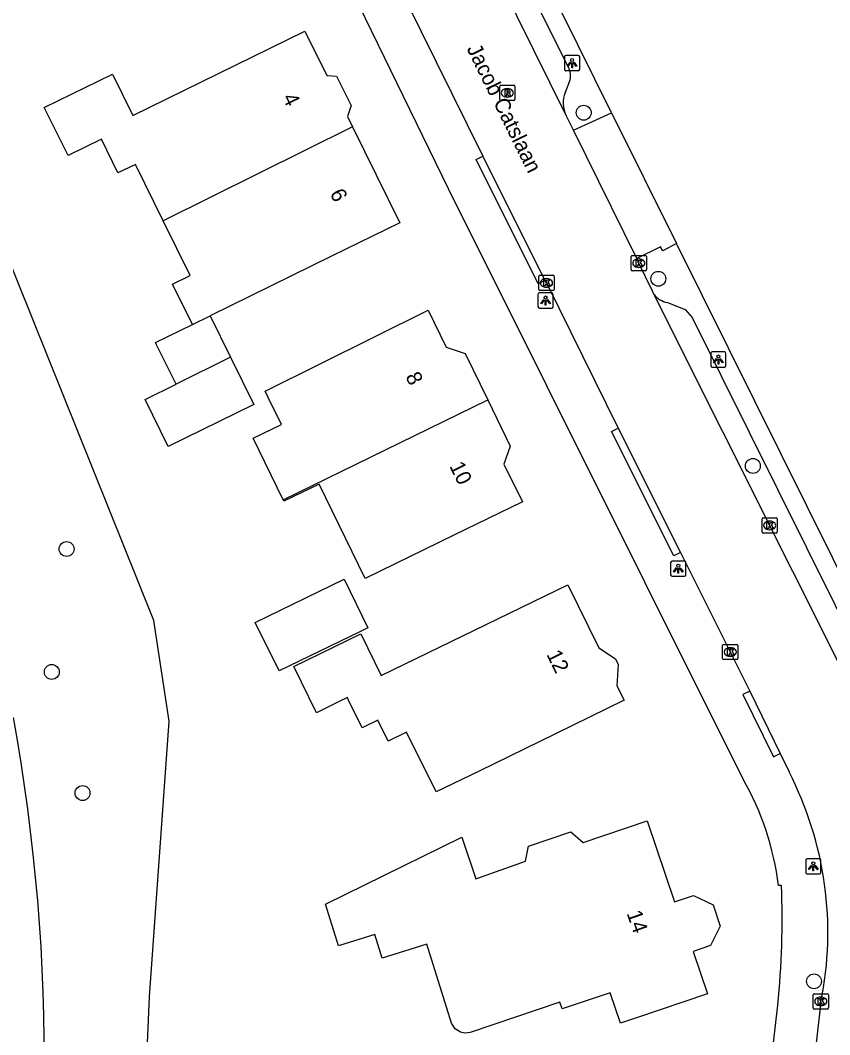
# Model space of a CAD drawing. Extents: x 161354 to 161876, y 382161 to 382804.
# Drawn here: x 161421.9 to 161475, y 382389.5 to 382456.1 of the extents above; entities that cross this region are included whole.
import ezdxf

# ---------------------------------------------------------------- set-up
doc = ezdxf.new("R2010")
doc.units = 0
for name, color, linetype in [('IMGEO_Boom', 7, 'Continuous'), ('IMGEO_Gemengd_bos', 7, 'Continuous'), ('IMGEO_Kolk', 7, 'Continuous'), ('IMGEO_Lichtpunt', 7, 'Continuous'), ('IMGEO_Openbare_ruimte_label', 7, 'Continuous'), ('IMGEO_Pand', 7, 'Continuous'), ('IMGEO_Pand_nummerreeks', 7, 'Continuous'), ('IMGEO_Rijbaan_lokaal_open', 7, 'Continuous'), ('IMGEO_Rioolput', 7, 'Continuous'), ('IMGEO_Voetpad_gesloten', 7, 'Continuous'), ('IMGEO_Voetpad_open', 7, 'Continuous')]:
    doc.layers.add(name, color=color, linetype=linetype)

msp = doc.modelspace()

# ---------------------------------------------------------------- linework, layer by layer
at = {"layer": 'IMGEO_Boom'}
for centre in [(161458.85, 382449.996), (161463.744, 382439.091), (161469.949, 382426.805), (161424.908, 382421.348), (161423.939, 382413.276), (161425.955, 382405.325), (161473.963, 382392.963)]:
    msp.add_circle(centre, 0.489, dxfattribs=at)
at = {"layer": 'IMGEO_Gemengd_bos'}
msp.add_lwpolyline([(161435.54, 382329.392), (161434.865, 382334.273), (161432.222, 382351.93), (161428.6, 382351.546), (161430.361, 382391.947), (161431.642, 382410.034), (161430.625, 382416.654), (161414.695, 382456.317), (161414.039, 382457.95), (161407.235, 382474.367), (161405.55, 382478.433), (161404.982, 382479.804)], dxfattribs=at)
at = {"layer": 'IMGEO_Kolk'}
for p, q in [((161461.963, 382439.692), (161461.963, 382440.544)), ((161462.038, 382440.618), (161462.89, 382440.618)), ((161462.964, 382440.544), (161462.964, 382439.692)), ((161462.474, 382439.838), (161462.449, 382439.838)), ((161462.451, 382440.398), (161462.476, 382440.398)), ((161455.902, 382438.394), (161455.902, 382439.246)), ((161455.977, 382439.32), (161456.829, 382439.32)), ((161456.903, 382439.246), (161456.903, 382438.394)), ((161462.89, 382439.618), (161462.038, 382439.618)), ((161456.413, 382438.54), (161456.388, 382438.54)), ((161456.39, 382439.1), (161456.415, 382439.1)), ((161456.829, 382438.32), (161455.977, 382438.32)), ((161470.553, 382422.471), (161470.553, 382423.323)), ((161470.628, 382423.397), (161471.48, 382423.397)), ((161471.041, 382423.177), (161471.066, 382423.177)), ((161471.554, 382423.323), (161471.554, 382422.471)), ((161471.064, 382422.617), (161471.039, 382422.617)), ((161471.48, 382422.397), (161470.628, 382422.397)), ((161467.966, 382414.16), (161467.966, 382415.012)), ((161468.041, 382415.086), (161468.893, 382415.086)), ((161468.454, 382414.866), (161468.479, 382414.866)), ((161468.967, 382415.012), (161468.967, 382414.16)), ((161468.893, 382414.086), (161468.041, 382414.086)), ((161468.477, 382414.306), (161468.452, 382414.306)), ((161473.906, 382391.218), (161473.906, 382392.07)), ((161473.981, 382392.144), (161474.833, 382392.144)), ((161474.394, 382391.924), (161474.419, 382391.924)), ((161474.907, 382392.07), (161474.907, 382391.218)), ((161474.417, 382391.364), (161474.392, 382391.364)), ((161474.833, 382391.144), (161473.981, 382391.144))]:
    msp.add_line(p, q, dxfattribs=at)
for points in [[(161461.963, 382439.692), (161461.963, 382440.544)], [(161462.038, 382440.618), (161462.89, 382440.618)], [(161462.964, 382440.544), (161462.964, 382439.692)], [(161462.284, 382440.318), (161462.407, 382440.318), (161462.407, 382440.167), (161462.537, 382440.318), (161462.701, 382440.318), (161462.555, 382440.167), (161462.708, 382439.918), (161462.556, 382439.918), (161462.471, 382440.082), (161462.407, 382440.015), (161462.407, 382439.918), (161462.284, 382439.918), (161462.284, 382440.318)], [(161455.902, 382438.394), (161455.902, 382439.246)], [(161455.977, 382439.32), (161456.829, 382439.32)], [(161456.903, 382439.246), (161456.903, 382438.394)], [(161462.89, 382439.618), (161462.038, 382439.618)], [(161456.223, 382439.02), (161456.346, 382439.02), (161456.346, 382438.869), (161456.476, 382439.02), (161456.64, 382439.02), (161456.494, 382438.869), (161456.647, 382438.62), (161456.495, 382438.62), (161456.41, 382438.784), (161456.346, 382438.717), (161456.346, 382438.62), (161456.223, 382438.62), (161456.223, 382439.02)], [(161456.829, 382438.32), (161455.977, 382438.32)], [(161470.553, 382422.471), (161470.553, 382423.323)], [(161470.628, 382423.397), (161471.48, 382423.397)], [(161471.554, 382423.323), (161471.554, 382422.471)], [(161470.874, 382423.097), (161470.997, 382423.097), (161470.997, 382422.946), (161471.127, 382423.097), (161471.291, 382423.097), (161471.145, 382422.946), (161471.298, 382422.697), (161471.146, 382422.697), (161471.061, 382422.861), (161470.997, 382422.794), (161470.997, 382422.697), (161470.874, 382422.697), (161470.874, 382423.097)], [(161471.48, 382422.397), (161470.628, 382422.397)], [(161467.966, 382414.16), (161467.966, 382415.012)], [(161468.041, 382415.086), (161468.893, 382415.086)], [(161468.287, 382414.786), (161468.41, 382414.786), (161468.41, 382414.635), (161468.54, 382414.786), (161468.704, 382414.786), (161468.558, 382414.635), (161468.711, 382414.386), (161468.559, 382414.386), (161468.474, 382414.55), (161468.41, 382414.483), (161468.41, 382414.386), (161468.287, 382414.386), (161468.287, 382414.786)], [(161468.967, 382415.012), (161468.967, 382414.16)], [(161468.893, 382414.086), (161468.041, 382414.086)], [(161473.906, 382391.218), (161473.906, 382392.07)], [(161473.981, 382392.144), (161474.833, 382392.144)], [(161474.907, 382392.07), (161474.907, 382391.218)], [(161474.227, 382391.844), (161474.35, 382391.844), (161474.35, 382391.693), (161474.48, 382391.844), (161474.644, 382391.844), (161474.498, 382391.693), (161474.651, 382391.444), (161474.499, 382391.444), (161474.414, 382391.608), (161474.35, 382391.541), (161474.35, 382391.444), (161474.227, 382391.444), (161474.227, 382391.844)], [(161474.833, 382391.144), (161473.981, 382391.144)]]:
    msp.add_lwpolyline(points, dxfattribs=at)
for centre, start, end in [((161462.04, 382440.542), 91.55205, 178.44795), ((161462.04, 382440.542), 91.55205, 178.44795), ((161462.888, 382440.542), 1.55205, 88.44795), ((161462.888, 382440.542), 1.55205, 88.44795), ((161455.979, 382439.244), 91.55205, 178.44795), ((161455.979, 382439.244), 91.55205, 178.44795), ((161456.827, 382439.244), 1.55205, 88.44795), ((161456.827, 382439.244), 1.55205, 88.44795), ((161462.04, 382439.694), 181.55205, 268.44795), ((161462.04, 382439.694), 181.55205, 268.44795), ((161462.888, 382439.694), 271.55205, 358.44795), ((161462.888, 382439.694), 271.55205, 358.44795), ((161455.979, 382438.396), 181.55205, 268.44795), ((161455.979, 382438.396), 181.55205, 268.44795), ((161456.827, 382438.396), 271.55205, 358.44795), ((161456.827, 382438.396), 271.55205, 358.44795), ((161470.63, 382423.321), 91.55205, 178.44795), ((161470.63, 382423.321), 91.55205, 178.44795), ((161471.478, 382423.321), 1.55205, 88.44795), ((161471.478, 382423.321), 1.55205, 88.44795), ((161470.63, 382422.473), 181.55205, 268.44795), ((161470.63, 382422.473), 181.55205, 268.44795), ((161471.478, 382422.473), 271.55205, 358.44795), ((161471.478, 382422.473), 271.55205, 358.44795), ((161468.043, 382415.01), 91.55205, 178.44795), ((161468.043, 382415.01), 91.55205, 178.44795), ((161468.891, 382415.01), 1.55205, 88.44795), ((161468.891, 382415.01), 1.55205, 88.44795), ((161468.043, 382414.162), 181.55205, 268.44795), ((161468.043, 382414.162), 181.55205, 268.44795), ((161468.891, 382414.162), 271.55205, 358.44795), ((161468.891, 382414.162), 271.55205, 358.44795), ((161473.983, 382392.068), 91.55205, 178.44795), ((161473.983, 382392.068), 91.55205, 178.44795), ((161474.831, 382392.068), 1.55205, 88.44795), ((161474.831, 382392.068), 1.55205, 88.44795), ((161473.983, 382391.22), 181.55205, 268.44795), ((161473.983, 382391.22), 181.55205, 268.44795), ((161474.831, 382391.22), 271.55205, 358.44795), ((161474.831, 382391.22), 271.55205, 358.44795)]:
    msp.add_arc(centre, 0.0765, start, end, dxfattribs=at)
for centre, major_axis, ratio, start_param, end_param in [((161462.45, 382440.118), (-0.387, 0.002), 0.722429, 4.712389, 7.853982), ((161462.475, 382440.118), (-0.39, 0.002), 0.717154, 1.570796, 4.712389), ((161456.389, 382438.82), (-0.387, 0.002), 0.722429, 4.712389, 7.853982), ((161456.414, 382438.82), (-0.39, 0.002), 0.717154, 1.570796, 4.712389), ((161471.04, 382422.897), (-0.387, 0.002), 0.722429, 4.712389, 7.853982), ((161471.065, 382422.897), (-0.39, 0.002), 0.717154, 1.570796, 4.712389), ((161468.453, 382414.586), (-0.387, 0.002), 0.722429, 4.712389, 7.853982), ((161468.478, 382414.586), (-0.39, 0.002), 0.717154, 1.570796, 4.712389), ((161474.393, 382391.644), (-0.387, 0.002), 0.722429, 4.712389, 7.853982), ((161474.418, 382391.644), (-0.39, 0.002), 0.717154, 1.570796, 4.712389)]:
    msp.add_ellipse(centre, major_axis=major_axis, ratio=ratio, start_param=start_param, end_param=end_param, dxfattribs=at)
at = {"layer": 'IMGEO_Lichtpunt'}
for p, q in [((161457.588, 382453.658), (161457.588, 382452.851)), ((161457.588, 382453.658), (161457.588, 382452.851)), ((161458.49, 382453.753), (161457.682, 382453.753)), ((161458.49, 382453.753), (161457.682, 382453.753)), ((161458.584, 382452.851), (161458.584, 382453.658)), ((161458.584, 382452.851), (161458.584, 382453.658)), ((161457.682, 382452.757), (161458.49, 382452.757)), ((161457.682, 382452.757), (161458.49, 382452.757)), ((161455.847, 382438.07), (161455.847, 382437.263)), ((161455.847, 382438.07), (161455.847, 382437.263)), ((161456.749, 382438.165), (161455.941, 382438.165)), ((161456.749, 382438.165), (161455.941, 382438.165)), ((161456.843, 382437.263), (161456.843, 382438.07)), ((161456.843, 382437.263), (161456.843, 382438.07)), ((161455.941, 382437.169), (161456.749, 382437.169)), ((161455.941, 382437.169), (161456.749, 382437.169)), ((161467.189, 382434.196), (161467.189, 382433.389)), ((161467.189, 382434.196), (161467.189, 382433.389)), ((161468.091, 382434.291), (161467.283, 382434.291)), ((161468.091, 382434.291), (161467.283, 382434.291)), ((161468.185, 382433.389), (161468.185, 382434.196)), ((161468.185, 382433.389), (161468.185, 382434.196)), ((161467.283, 382433.295), (161468.091, 382433.295)), ((161467.283, 382433.295), (161468.091, 382433.295)), ((161465.456, 382420.555), (161464.648, 382420.555)), ((161465.456, 382420.555), (161464.648, 382420.555)), ((161464.554, 382420.46), (161464.554, 382419.653)), ((161464.554, 382420.46), (161464.554, 382419.653)), ((161465.55, 382419.653), (161465.55, 382420.46)), ((161465.55, 382419.653), (161465.55, 382420.46)), ((161464.648, 382419.559), (161465.456, 382419.559)), ((161464.648, 382419.559), (161465.456, 382419.559)), ((161473.415, 382400.92), (161473.415, 382400.113)), ((161473.415, 382400.92), (161473.415, 382400.113)), ((161474.317, 382401.015), (161473.509, 382401.015)), ((161474.317, 382401.015), (161473.509, 382401.015)), ((161474.411, 382400.113), (161474.411, 382400.92)), ((161474.411, 382400.113), (161474.411, 382400.92)), ((161473.509, 382400.019), (161474.317, 382400.019)), ((161473.509, 382400.019), (161474.317, 382400.019))]:
    msp.add_line(p, q, dxfattribs=at)
for points in [[(161457.962, 382453.322), (161458.001, 382453.294), (161457.813, 382453.032), (161457.775, 382453.059), (161457.962, 382453.322)], [(161458.064, 382453.274), (161458.111, 382453.274), (161458.111, 382452.952), (161458.064, 382452.952), (161458.064, 382453.274)], [(161458.174, 382453.294), (161458.212, 382453.321), (161458.399, 382453.059), (161458.36, 382453.031), (161458.174, 382453.294)], [(161456.221, 382437.734), (161456.26, 382437.706), (161456.072, 382437.444), (161456.034, 382437.471), (161456.221, 382437.734)], [(161456.323, 382437.686), (161456.37, 382437.686), (161456.37, 382437.364), (161456.323, 382437.364), (161456.323, 382437.686)], [(161456.433, 382437.706), (161456.471, 382437.733), (161456.658, 382437.471), (161456.619, 382437.443), (161456.433, 382437.706)], [(161467.563, 382433.86), (161467.602, 382433.832), (161467.414, 382433.57), (161467.376, 382433.597), (161467.563, 382433.86)], [(161467.775, 382433.832), (161467.813, 382433.859), (161468, 382433.597), (161467.961, 382433.569), (161467.775, 382433.832)], [(161467.665, 382433.812), (161467.712, 382433.812), (161467.712, 382433.49), (161467.665, 382433.49), (161467.665, 382433.812)], [(161464.928, 382420.124), (161464.967, 382420.096), (161464.779, 382419.834), (161464.741, 382419.861), (161464.928, 382420.124)], [(161465.03, 382420.076), (161465.077, 382420.076), (161465.077, 382419.754), (161465.03, 382419.754), (161465.03, 382420.076)], [(161465.14, 382420.096), (161465.178, 382420.123), (161465.365, 382419.861), (161465.326, 382419.833), (161465.14, 382420.096)], [(161473.789, 382400.584), (161473.828, 382400.556), (161473.64, 382400.294), (161473.602, 382400.321), (161473.789, 382400.584)], [(161473.891, 382400.536), (161473.938, 382400.536), (161473.938, 382400.214), (161473.891, 382400.214), (161473.891, 382400.536)], [(161474.001, 382400.556), (161474.039, 382400.583), (161474.226, 382400.321), (161474.187, 382400.293), (161474.001, 382400.556)]]:
    msp.add_lwpolyline(points, dxfattribs=at)
for centre in [(161458.087, 382453.456), (161456.346, 382437.868), (161467.688, 382433.994), (161465.053, 382420.258), (161473.914, 382400.718)]:
    msp.add_circle(centre, 0.0994, dxfattribs=at)
for centre, start, end in [((161457.682, 382453.658), 90, 180), ((161457.682, 382453.658), 90, 180), ((161458.49, 382453.658), 0, 90), ((161458.49, 382453.658), 0, 90), ((161457.682, 382452.851), 180, 270), ((161457.682, 382452.851), 180, 270), ((161458.49, 382452.851), 270, 0), ((161458.49, 382452.851), 270, 360), ((161455.941, 382438.07), 90, 180), ((161455.941, 382438.07), 90, 180), ((161456.749, 382438.07), 0, 90), ((161456.749, 382438.07), 0, 90), ((161455.941, 382437.263), 180, 270), ((161455.941, 382437.263), 180, 270), ((161456.749, 382437.263), 270, 0), ((161456.749, 382437.263), 270, 360), ((161467.283, 382434.196), 90, 180), ((161467.283, 382434.196), 90, 180), ((161468.091, 382434.196), 0, 90), ((161468.091, 382434.196), 0, 90), ((161467.283, 382433.389), 180, 270), ((161467.283, 382433.389), 180, 270), ((161468.091, 382433.389), 270, 0), ((161468.091, 382433.389), 270, 360), ((161464.648, 382420.46), 90, 180), ((161464.648, 382420.46), 90, 180), ((161465.456, 382420.46), 0, 90), ((161465.456, 382420.46), 0, 90), ((161464.648, 382419.653), 180, 270), ((161464.648, 382419.653), 180, 270), ((161465.456, 382419.653), 270, 0), ((161465.456, 382419.653), 270, 360), ((161473.509, 382400.92), 90, 180), ((161473.509, 382400.92), 90, 180), ((161474.317, 382400.92), 0, 90), ((161474.317, 382400.92), 0, 90), ((161473.509, 382400.113), 180, 270), ((161473.509, 382400.113), 180, 270), ((161474.317, 382400.113), 270, 0), ((161474.317, 382400.113), 270, 360)]:
    msp.add_arc(centre, 0.0946, start, end, dxfattribs=at)
at = {"layer": 'IMGEO_Pand'}
for points in [[(161431.249, 382442.9), (161429.429, 382446.606), (161428.274, 382446.039), (161427.19, 382448.248), (161425.022, 382447.182), (161423.428, 382450.334), (161427.916, 382452.537), (161429.259, 382449.803), (161440.551, 382455.345), (161441.981, 382452.448), (161442.63, 382452.406), (161443.584, 382450.471), (161443.34, 382449.75), (161443.679, 382449.063)], [(161443.679, 382449.063), (161431.249, 382442.9)], [(161443.679, 382449.063), (161446.786, 382442.77), (161442.298, 382440.567), (161434.323, 382436.652)], [(161433.166, 382436.084), (161431.862, 382438.735), (161433.016, 382439.301), (161431.249, 382442.9)], [(161433.166, 382436.084), (161434.323, 382436.652)], [(161434.323, 382436.652), (161435.656, 382433.942)], [(161439.129, 382424.581), (161437.153, 382428.628), (161439.003, 382429.531), (161438.143, 382431.292), (161437.938, 382431.713), (161448.648, 382437.024), (161449.829, 382434.606), (161451.059, 382434.183), (161452.547, 382431.133)], [(161432.091, 382432.175), (161430.818, 382434.763), (161430.751, 382434.899), (161433.166, 382436.084)], [(161435.656, 382433.942), (161437.188, 382430.826), (161431.577, 382428.087), (161430.07, 382431.173), (161432.091, 382432.175)], [(161435.656, 382433.942), (161432.091, 382432.175)], [(161452.547, 382431.133), (161454.023, 382428.11), (161453.615, 382426.921), (161454.824, 382424.443), (161450.331, 382422.25), (161444.511, 382419.408), (161441.484, 382425.608), (161439.177, 382424.482), (161439.129, 382424.581)], [(161439.129, 382424.581), (161452.547, 382431.133)], [(161437.289, 382416.531), (161443.136, 382419.368), (161444.686, 382416.174), (161444.155, 382415.916), (161438.856, 382413.342), (161437.289, 382416.531)], [(161446.011, 382408.735), (161445.339, 382410.102), (161444.314, 382409.598), (161443.421, 382411.414), (161443.335, 382411.588), (161442.761, 382411.305), (161441.308, 382410.591), (161439.814, 382413.629), (161444.225, 382415.772), (161445.552, 382413.037), (161457.816, 382418.992), (161459.846, 382414.863), (161460.93, 382414.137), (161461.118, 382413.755), (161461.026, 382412.37), (161461.493, 382411.419), (161457.007, 382409.213), (161451.995, 382406.763), (161449.159, 382405.394), (161447.223, 382409.331), (161446.011, 382408.735)], [(161442.756, 382395.294), (161441.902, 382398.039), (161450.849, 382402.431), (161451.777, 382399.69), (161455.034, 382400.846), (161455.233, 382401.844), (161458.004, 382402.783), (161458.811, 382402.074), (161463.01, 382403.497), (161464.811, 382398.182), (161466.063, 382398.606), (161467.338, 382397.976), (161467.81, 382396.584), (161467.178, 382395.304), (161466.037, 382394.917), (161466.977, 382392.145), (161462.242, 382390.54), (161461.258, 382390.207), (161460.577, 382392.215), (161457.433, 382391.149), (161457.279, 382391.604), (161451.403, 382389.612), (161451.041, 382389.561), (161450.751, 382389.62), (161450.413, 382389.832), (161450.165, 382390.222), (161448.556, 382395.4), (161445.624, 382394.489), (161445.143, 382396.036), (161442.756, 382395.294)]]:
    msp.add_lwpolyline(points, dxfattribs=at)
at = {"layer": 'IMGEO_Rijbaan_lokaal_open'}
for points in [[(161457.689, 382449.818), (161441.548, 382482.463), (161440.761, 382484.044)], [(161447.12, 382457.484), (161452.227, 382447.149)], [(161458.175, 382448.856), (161457.689, 382449.818)], [(161462.329, 382440.433), (161458.175, 382448.856)], [(161452.227, 382447.149), (161456.306, 382438.986)], [(161463.455, 382438.086), (161463.358, 382438.279), (161462.466, 382440.119), (161462.329, 382440.433)], [(161456.306, 382438.986), (161456.426, 382438.783), (161461.114, 382429.288)], [(161477.113, 382410.786), (161463.455, 382438.086)], [(161461.114, 382429.288), (161465.21, 382421.123)], [(161465.21, 382421.123), (161469.744, 382412.024)], [(161469.744, 382412.024), (161471.751, 382407.93)], [(161471.751, 382407.93), (161472.321, 382406.713)], [(161474.412, 382391.584), (161473.921, 382387.39), (161473.27, 382381.594), (161472.852, 382378.01), (161472.288, 382368.966), (161472.129, 382362.118)]]:
    msp.add_lwpolyline(points, dxfattribs=at)
msp.add_arc((161451.842, 382396.174), 23.032, 348.50595, 27.2322, dxfattribs=at)
at = {"layer": 'IMGEO_Rioolput'}
for p, q in [((161453.332, 382450.874), (161453.332, 382451.726)), ((161453.407, 382451.8), (161454.259, 382451.8)), ((161453.82, 382451.58), (161453.845, 382451.58)), ((161454.333, 382451.726), (161454.333, 382450.874)), ((161454.259, 382450.8), (161453.407, 382450.8)), ((161453.843, 382451.02), (161453.818, 382451.02))]:
    msp.add_line(p, q, dxfattribs=at)
for points in [[(161453.332, 382450.874), (161453.332, 382451.726)], [(161453.407, 382451.8), (161454.259, 382451.8)], [(161453.921, 382451.498), (161453.669, 382451.5), (161453.669, 382451.1)], [(161453.669, 382451.1), (161453.793, 382451.1), (161453.793, 382451.262), (161453.804, 382451.262)], [(161453.847, 382451.419), (161453.793, 382451.419), (161453.793, 382451.338)], [(161453.793, 382451.338), (161453.845, 382451.338)], [(161453.851, 382451.233), (161453.922, 382451.1), (161454.062, 382451.1), (161453.997, 382451.226)], [(161454.333, 382451.726), (161454.333, 382450.874)], [(161454.259, 382450.8), (161453.407, 382450.8)]]:
    msp.add_lwpolyline(points, dxfattribs=at)
for centre, radius, start, end in [((161453.409, 382451.724), 0.0765, 91.55205, 178.44795), ((161453.409, 382451.724), 0.0765, 91.55205, 178.44795), ((161453.803, 382451.209), 0.0533, 26.02933, 88.69889), ((161453.829, 382451.527), 0.19, 274.7715, 282.96867), ((161453.853, 382451.323), 0.0964, 77.00612, 93.18647), ((161453.867, 382451.38), 0.0378, 276.66336, 79.67722), ((161453.92, 382451.388), 0.109, 350.36119, 89.41601), ((161453.918, 382451.388), 0.112, 277.58423, 350.98172), ((161453.902, 382451.173), 0.108, 29.51342, 73.79051), ((161454.257, 382451.724), 0.0765, 1.55205, 88.44795), ((161454.257, 382451.724), 0.0765, 1.55205, 88.44795), ((161453.409, 382450.876), 0.0765, 181.55205, 268.44795), ((161453.409, 382450.876), 0.0765, 181.55205, 268.44795), ((161454.257, 382450.876), 0.0765, 271.55205, 358.44795), ((161454.257, 382450.876), 0.0765, 271.55205, 358.44795)]:
    msp.add_arc(centre, radius, start, end, dxfattribs=at)
for centre, major_axis, ratio, start_param, end_param in [((161453.819, 382451.3), (-0.387, 0.002), 0.722429, 4.712389, 7.853982), ((161453.844, 382451.3), (-0.39, 0.002), 0.717154, 1.570796, 4.712389)]:
    msp.add_ellipse(centre, major_axis=major_axis, ratio=ratio, start_param=start_param, end_param=end_param, dxfattribs=at)
at = {"layer": 'IMGEO_Voetpad_gesloten'}
msp.add_arc((161296.873, 382387.678), 126.584, 348.34037, 10.29268, dxfattribs=at)
at = {"layer": 'IMGEO_Voetpad_open'}
for points in [[(161469.314, 382406.236), (161449.97, 382444.999), (161439.035, 382467.472), (161429.86, 382485.658), (161426.786, 382491.905), (161423.96, 382492.581)], [(161460.674, 382449.996), (161457.359, 382456.669), (161443.651, 382484.283)], [(161443.197, 382482.422), (161457.882, 382452.893)], [(161457.925, 382452.062), (161457.628, 382451.313)], [(161458.175, 382448.856), (161460.674, 382449.996)], [(161460.674, 382449.996), (161464.946, 382441.398)], [(161456.306, 382438.986), (161455.859, 382438.763), (161451.78, 382446.926), (161452.227, 382447.149)], [(161464.946, 382441.398), (161464.031, 382440.935), (161463.885, 382441.184), (161462.329, 382440.433)], [(161480.33, 382410.398), (161464.946, 382441.398)], [(161464.352, 382437.542), (161465.51, 382437.074), (161465.956, 382436.55), (161477.208, 382413.913)], [(161465.21, 382421.123), (161464.764, 382420.899), (161460.668, 382429.064), (161461.114, 382429.288)], [(161469.744, 382412.024), (161469.296, 382411.804), (161471.303, 382407.71), (161471.751, 382407.93)], [(161471.826, 382399.25), (161471.626, 382399.262)], [(161469.389, 382360.877), (161469.78, 382373.623), (161470.522, 382382.134), (161471.59, 382391.404)]]:
    msp.add_lwpolyline(points, dxfattribs=at)
for centre, radius, start, end in [((161456.813, 382452.421), 1.169, 342.10399, 23.82026), ((161459.452, 382450.639), 1.945, 159.71425, 204.9588), ((161464.531, 382438.848), 1.319, 215.32447, 262.20476), ((161452.968, 382396.947), 18.801, 7.07341, 29.60907), ((161415.607, 382397.014), 56.263, 354.27705, 2.27718)]:
    msp.add_arc(centre, radius, start, end, dxfattribs=at)

# ---------------------------------------------------------------- texts
at = {"layer": 'IMGEO_Openbare_ruimte_label'}
msp.add_text('Jacob Catslaan', height=1, rotation=296.28331, dxfattribs=at).set_placement((161451.147, 382454.209))
at = {"layer": 'IMGEO_Pand_nummerreeks'}
for s, rotation, p in [('4', 296.37304, (161439.049, 382450.991)), ('6', 296.37304, (161442.166, 382444.704)), ('8', 296.14385, (161447.128, 382432.677)), ('10', 296.14637, (161450.013, 382426.8)), ('12', 295.89748, (161456.382, 382414.437)), ('14', 289.26216, (161461.655, 382397.432))]:
    msp.add_text(s, height=1, rotation=rotation, dxfattribs=at).set_placement(p)

doc.saveas('drawing.dxf')
